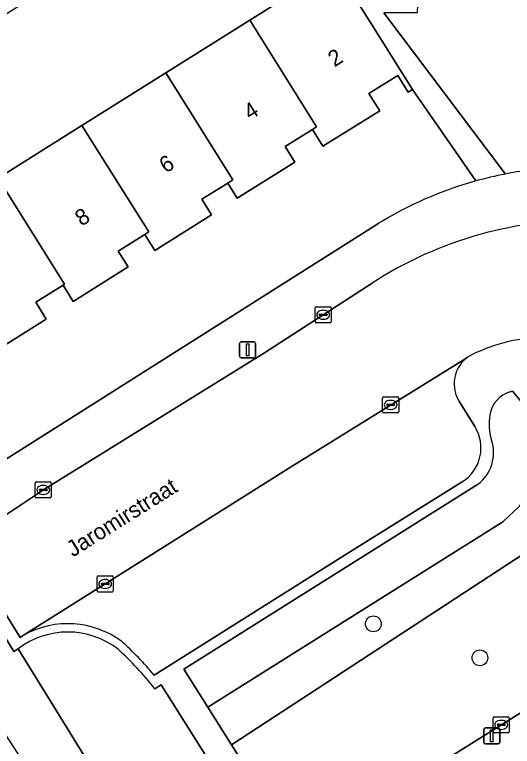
# Model space of a CAD drawing. Extents: x 160077 to 160948, y 386481 to 387498.
# Drawn here: x 160562.4 to 160593.35, y 386604.57 to 386650.13 of the extents above; entities that cross this region are included whole.
import ezdxf

# ---------------------------------------------------------------- set-up
doc = ezdxf.new("R2010")
doc.units = 0
for name, color, linetype in [('IMGEO_Boom', 7, 'Continuous'), ('IMGEO_Erf', 7, 'Continuous'), ('IMGEO_Groenvoorziening', 7, 'Continuous'), ('IMGEO_Kolk', 7, 'Continuous'), ('IMGEO_Lichtmast', 7, 'Continuous'), ('IMGEO_Openbare_ruimte_label', 7, 'Continuous'), ('IMGEO_Pand', 7, 'Continuous'), ('IMGEO_Pand_nummerreeks', 7, 'Continuous'), ('IMGEO_Parkeervlak_open', 7, 'Continuous'), ('IMGEO_Rijbaan_lokaal_open', 7, 'Continuous'), ('IMGEO_Voetpad_open', 7, 'Continuous')]:
    doc.layers.add(name, color=color, linetype=linetype)

msp = doc.modelspace()

# ---------------------------------------------------------------- linework, layer by layer
at = {"layer": 'IMGEO_Boom'}
for centre in [(160584.707, 386612.197), (160591.337, 386610.081)]:
    msp.add_circle(centre, 0.489, dxfattribs=at)
at = {"layer": 'IMGEO_Erf'}
for points in [[(160596.599, 386677.441), (160596.859, 386683.778), (160590.518, 386683.487), (160585.352, 386682.36), (160577.456, 386680.637), (160577.409, 386679.381), (160587.176, 386678.997), (160587.075, 386676.42), (160577.308, 386676.804), (160578.878, 386670.063), (160582.758, 386670.009), (160582.777, 386670.009), (160582.54, 386664.36), (160582.425, 386661.598), (160580.436, 386661.556), (160581.591, 386656.538), (160587.64, 386656.538), (160587.486, 386651.864), (160587.433, 386650.24), (160585.361, 386650.24), (160592.917, 386640.202)], [(160571.801, 386646.502), (160577.019, 386649.777), (160582.341, 386653.116), (160579.976, 386656.903), (160578.066, 386663.398), (160575.291, 386661.665), (160576.679, 386659.497), (160572.571, 386656.868), (160568.508, 386654.268), (160567.121, 386656.435), (160564.914, 386655.022), (160566.242, 386652.948), (160562.134, 386650.319), (160558.071, 386647.719), (160556.684, 386649.886), (160554.477, 386648.473), (160555.805, 386646.399), (160551.696, 386643.77), (160547.634, 386641.17), (160546.247, 386643.337), (160543.649, 386641.674), (160557.447, 386619.675), (160584.982, 386637.094)], [(160591.082, 386639.771), (160587.14, 386645.468), (160586.871, 386645.299), (160586.222, 386646.333), (160584.432, 386645.21), (160585.102, 386644.143), (160581.576, 386641.93), (160580.917, 386642.979), (160579.221, 386641.915), (160579.831, 386640.943), (160576.247, 386638.694), (160575.653, 386639.642), (160574.036, 386638.627), (160574.643, 386637.659), (160571.121, 386635.449), (160570.5, 386636.44), (160568.843, 386635.401), (160569.463, 386634.414), (160566.044, 386632.269), (160565.409, 386633.28), (160563.712, 386632.215), (160564.367, 386631.172), (160560.876, 386628.982)], [(160561.363, 386639.953), (160566.582, 386643.228), (160571.801, 386646.502)]]:
    msp.add_lwpolyline(points, dxfattribs=at)
for centre, radius, start, end in [((160597.405, 386617.02), 23.612, 86.9009, 100.9581), ((160597.413, 386617.056), 23.58, 105.574, 121.8147)]:
    msp.add_arc(centre, radius, start, end, dxfattribs=at)
at = {"layer": 'IMGEO_Groenvoorziening'}
for points in [[(160593.353, 386626.675), (160594.006, 386625.92), (160594.659, 386624.737), (160595.039, 386622.809), (160594.777, 386621.167), (160594.444, 386620.452), (160593.826, 386619.548), (160592.769, 386618.557), (160574.42, 386607.003), (160575.89, 386604.664), (160595.095, 386617.234), (160597.492, 386622.596), (160596.919, 386627.153), (160596.284, 386627.12)], [(160603.036, 386627.12), (160598.454, 386627.234), (160596.919, 386627.153), (160597.492, 386622.596), (160595.095, 386617.234), (160575.89, 386604.664), (160580.063, 386598.024), (160599.738, 386610.339), (160602.696, 386611.053)], [(160591.194, 386620.874), (160572.93, 386609.373), (160574.42, 386607.003), (160592.769, 386618.557), (160593.826, 386619.548), (160594.444, 386620.452), (160594.777, 386621.167), (160595.039, 386622.809), (160594.659, 386624.737), (160594.006, 386625.92), (160593.353, 386626.675), (160593.289, 386626.657), (160593.225, 386626.638)], [(160562.612, 386610.642), (160569.745, 386599.077), (160575.219, 386602.514), (160571.515, 386608.404), (160571.115, 386608.154)]]:
    msp.add_lwpolyline(points, dxfattribs=at)
msp.add_lwpolyline([(160562.612, 386610.642), (160562.354, 386610.475), (160560.029, 386614.281), (160557.174, 386612.458), (160566.971, 386597.336), (160569.745, 386599.077)], close=True, dxfattribs=at)
for centre, radius, start, end in [((160593.714, 386624.927), 1.779, 105.9417, 171.0843), ((160595.098, 386624.624), 3.195, 169.5683, 197.9088), ((160589.706, 386622.857), 2.479, 306.8775, 18.4521), ((160565.705, 386606.587), 5.1, 52.2047, 127.3347), ((160555.455, 386595.923), 19.87, 37.9918, 47.6892)]:
    msp.add_arc(centre, radius, start, end, dxfattribs=at)
at = {"layer": 'IMGEO_Kolk'}
for p, q in [((160581.087, 386631.014), (160581.087, 386631.866)), ((160581.162, 386631.94), (160582.014, 386631.94)), ((160581.575, 386631.72), (160581.6, 386631.72)), ((160582.088, 386631.866), (160582.088, 386631.014)), ((160581.346, 386631.434), (160581.346, 386631.446)), ((160581.784, 386631.397), (160581.386, 386631.397)), ((160581.389, 386631.483), (160581.787, 386631.483)), ((160581.598, 386631.16), (160581.573, 386631.16)), ((160581.83, 386631.446), (160581.83, 386631.434)), ((160582.014, 386630.94), (160581.162, 386630.94)), ((160585.283, 386625.405), (160585.283, 386626.257)), ((160585.358, 386626.331), (160586.21, 386626.331)), ((160585.771, 386626.111), (160585.796, 386626.111)), ((160586.284, 386626.257), (160586.284, 386625.405)), ((160585.542, 386625.825), (160585.542, 386625.837)), ((160585.98, 386625.788), (160585.582, 386625.788)), ((160585.585, 386625.874), (160585.983, 386625.874)), ((160586.026, 386625.837), (160586.026, 386625.825)), ((160586.21, 386625.331), (160585.358, 386625.331)), ((160585.794, 386625.551), (160585.769, 386625.551)), ((160563.678, 386620.108), (160563.678, 386620.96)), ((160563.753, 386621.034), (160564.605, 386621.034)), ((160564.166, 386620.814), (160564.191, 386620.814)), ((160564.679, 386620.96), (160564.679, 386620.108)), ((160563.937, 386620.528), (160563.937, 386620.54)), ((160564.375, 386620.491), (160563.977, 386620.491)), ((160563.98, 386620.577), (160564.378, 386620.577)), ((160564.189, 386620.254), (160564.164, 386620.254)), ((160564.421, 386620.54), (160564.421, 386620.528)), ((160564.605, 386620.034), (160563.753, 386620.034)), ((160567.604, 386615.179), (160568.456, 386615.179)), ((160567.529, 386614.253), (160567.529, 386615.105)), ((160567.788, 386614.673), (160567.788, 386614.685)), ((160567.831, 386614.722), (160568.229, 386614.722)), ((160568.017, 386614.959), (160568.042, 386614.959)), ((160568.272, 386614.685), (160568.272, 386614.673)), ((160568.53, 386615.105), (160568.53, 386614.253)), ((160568.226, 386614.636), (160567.828, 386614.636)), ((160568.04, 386614.399), (160568.015, 386614.399)), ((160568.456, 386614.179), (160567.604, 386614.179)), ((160592.16, 386605.482), (160592.16, 386606.334)), ((160592.235, 386606.408), (160593.087, 386606.408)), ((160592.648, 386606.188), (160592.673, 386606.188)), ((160593.161, 386606.334), (160593.161, 386605.482)), ((160592.419, 386605.902), (160592.419, 386605.914)), ((160592.857, 386605.865), (160592.459, 386605.865)), ((160592.462, 386605.951), (160592.86, 386605.951)), ((160592.671, 386605.628), (160592.646, 386605.628)), ((160592.903, 386605.914), (160592.903, 386605.902)), ((160593.087, 386605.408), (160592.235, 386605.408))]:
    msp.add_line(p, q, dxfattribs=at)
for points in [[(160581.087, 386631.014), (160581.087, 386631.866)], [(160581.162, 386631.94), (160582.014, 386631.94)], [(160582.088, 386631.866), (160582.088, 386631.014)], [(160582.014, 386630.94), (160581.162, 386630.94)], [(160585.283, 386625.405), (160585.283, 386626.257)], [(160585.358, 386626.331), (160586.21, 386626.331)], [(160586.284, 386626.257), (160586.284, 386625.405)], [(160586.21, 386625.331), (160585.358, 386625.331)], [(160563.678, 386620.108), (160563.678, 386620.96)], [(160563.753, 386621.034), (160564.605, 386621.034)], [(160564.679, 386620.96), (160564.679, 386620.108)], [(160564.605, 386620.034), (160563.753, 386620.034)], [(160567.604, 386615.179), (160568.456, 386615.179)], [(160567.529, 386614.253), (160567.529, 386615.105)], [(160568.53, 386615.105), (160568.53, 386614.253)], [(160568.456, 386614.179), (160567.604, 386614.179)], [(160592.16, 386605.482), (160592.16, 386606.334)], [(160592.235, 386606.408), (160593.087, 386606.408)], [(160593.161, 386606.334), (160593.161, 386605.482)], [(160593.087, 386605.408), (160592.235, 386605.408)]]:
    msp.add_lwpolyline(points, dxfattribs=at)
for centre, radius, start, end in [((160581.164, 386631.864), 0.0765, 91.552, 178.448), ((160581.164, 386631.864), 0.0765, 91.552, 178.448), ((160582.012, 386631.864), 0.0765, 1.552, 88.448), ((160582.012, 386631.864), 0.0765, 1.552, 88.448), ((160581.386, 386631.443), 0.0403, 85.8775, 175.7526), ((160581.383, 386631.433), 0.0366, 178.938, 274.7102), ((160581.787, 386631.44), 0.043, 264.8664, 352.4533), ((160581.791, 386631.445), 0.0386, 1.7309, 96.639), ((160581.164, 386631.016), 0.0765, 181.552, 268.448), ((160581.164, 386631.016), 0.0765, 181.552, 268.448), ((160582.012, 386631.016), 0.0765, 271.552, 358.448), ((160582.012, 386631.016), 0.0765, 271.552, 358.448), ((160585.36, 386626.255), 0.0765, 91.552, 178.448), ((160585.36, 386626.255), 0.0765, 91.552, 178.448), ((160586.208, 386626.255), 0.0765, 1.552, 88.448), ((160586.208, 386626.255), 0.0765, 1.552, 88.448), ((160585.582, 386625.834), 0.0403, 85.8775, 175.7526), ((160585.579, 386625.824), 0.0366, 178.938, 274.7102), ((160585.983, 386625.831), 0.043, 264.8664, 352.4533), ((160585.987, 386625.836), 0.0386, 1.7309, 96.639), ((160585.36, 386625.407), 0.0765, 181.552, 268.448), ((160585.36, 386625.407), 0.0765, 181.552, 268.448), ((160586.208, 386625.407), 0.0765, 271.552, 358.448), ((160586.208, 386625.407), 0.0765, 271.552, 358.448), ((160563.755, 386620.958), 0.0765, 91.552, 178.448), ((160563.755, 386620.958), 0.0765, 91.552, 178.448), ((160564.603, 386620.958), 0.0765, 1.552, 88.448), ((160564.603, 386620.958), 0.0765, 1.552, 88.448), ((160563.977, 386620.537), 0.0403, 85.8775, 175.7526), ((160563.974, 386620.527), 0.0366, 178.938, 274.7102), ((160564.378, 386620.534), 0.043, 264.8664, 352.4533), ((160564.382, 386620.539), 0.0386, 1.7309, 96.639), ((160563.755, 386620.11), 0.0765, 181.552, 268.448), ((160563.755, 386620.11), 0.0765, 181.552, 268.448), ((160564.603, 386620.11), 0.0765, 271.552, 358.448), ((160564.603, 386620.11), 0.0765, 271.552, 358.448), ((160567.606, 386615.103), 0.0765, 91.552, 178.448), ((160567.606, 386615.103), 0.0765, 91.552, 178.448), ((160568.454, 386615.103), 0.0765, 1.552, 88.448), ((160568.454, 386615.103), 0.0765, 1.552, 88.448), ((160567.828, 386614.682), 0.0403, 85.8775, 175.7526), ((160567.825, 386614.672), 0.0366, 178.938, 274.7102), ((160568.229, 386614.679), 0.043, 264.8664, 352.4533), ((160568.233, 386614.684), 0.0386, 1.7309, 96.639), ((160567.606, 386614.255), 0.0765, 181.552, 268.448), ((160567.606, 386614.255), 0.0765, 181.552, 268.448), ((160568.454, 386614.255), 0.0765, 271.552, 358.448), ((160568.454, 386614.255), 0.0765, 271.552, 358.448), ((160592.237, 386606.332), 0.0765, 91.552, 178.448), ((160592.237, 386606.332), 0.0765, 91.552, 178.448), ((160593.085, 386606.332), 0.0765, 1.552, 88.448), ((160593.085, 386606.332), 0.0765, 1.552, 88.448), ((160592.459, 386605.911), 0.0403, 85.8775, 175.7526), ((160592.456, 386605.901), 0.0366, 178.938, 274.7102), ((160592.86, 386605.908), 0.043, 264.8664, 352.4533), ((160592.864, 386605.913), 0.0386, 1.7309, 96.639), ((160592.237, 386605.484), 0.0765, 181.552, 268.448), ((160592.237, 386605.484), 0.0765, 181.552, 268.448), ((160593.085, 386605.484), 0.0765, 271.552, 358.448), ((160593.085, 386605.484), 0.0765, 271.552, 358.448)]:
    msp.add_arc(centre, radius, start, end, dxfattribs=at)
for centre, major_axis, ratio, start_param, end_param in [((160581.574, 386631.44), (-0.387, 0.002), 0.722429, 4.712389, 7.853982), ((160581.599, 386631.44), (-0.39, 0.002), 0.717154, 1.570796, 4.712389), ((160585.77, 386625.831), (-0.387, 0.002), 0.722429, 4.712389, 7.853982), ((160585.795, 386625.831), (-0.39, 0.002), 0.717154, 1.570796, 4.712389), ((160564.165, 386620.534), (-0.387, 0.002), 0.722429, 4.712389, 7.853982), ((160564.19, 386620.534), (-0.39, 0.002), 0.717154, 1.570796, 4.712389), ((160568.016, 386614.679), (-0.387, 0.002), 0.722429, 4.712389, 7.853982), ((160568.041, 386614.679), (-0.39, 0.002), 0.717154, 1.570796, 4.712389), ((160592.647, 386605.908), (-0.387, 0.002), 0.722429, 4.712389, 7.853982), ((160592.672, 386605.908), (-0.39, 0.002), 0.717154, 1.570796, 4.712389)]:
    msp.add_ellipse(centre, major_axis=major_axis, ratio=ratio, start_param=start_param, end_param=end_param, dxfattribs=at)
at = {"layer": 'IMGEO_Lichtmast'}
for p, q in [((160576.489, 386629.76), (160577.279, 386629.76)), ((160577.279, 386629.76), (160576.489, 386629.76)), ((160576.389, 386628.86), (160576.389, 386629.66)), ((160576.389, 386629.66), (160576.389, 386628.86)), ((160577.379, 386629.66), (160577.379, 386628.86)), ((160577.379, 386628.86), (160577.379, 386629.66)), ((160577.279, 386628.76), (160576.489, 386628.76)), ((160576.489, 386628.76), (160577.279, 386628.76)), ((160591.577, 386604.817), (160591.577, 386605.617)), ((160591.577, 386605.617), (160591.577, 386604.817)), ((160591.677, 386605.717), (160592.467, 386605.717)), ((160592.467, 386605.717), (160591.677, 386605.717)), ((160592.567, 386605.617), (160592.567, 386604.817)), ((160592.567, 386604.817), (160592.567, 386605.617)), ((160592.467, 386604.717), (160591.677, 386604.717)), ((160591.677, 386604.717), (160592.467, 386604.717))]:
    msp.add_line(p, q, dxfattribs=at)
for points in [[(160576.809, 386629.635), (160576.959, 386629.635), (160576.959, 386628.885), (160576.809, 386628.885), (160576.809, 386629.635)], [(160591.997, 386605.592), (160592.147, 386605.592), (160592.147, 386604.842), (160591.997, 386604.842), (160591.997, 386605.592)]]:
    msp.add_lwpolyline(points, dxfattribs=at)
for centre, start, end in [((160576.489, 386629.66), 90, 180), ((160576.489, 386629.66), 90, 180), ((160577.279, 386629.66), 0, 90), ((160577.279, 386629.66), 360, 90), ((160576.489, 386628.86), 180, 270), ((160576.489, 386628.86), 180, 270), ((160577.279, 386628.86), 270, 0), ((160577.279, 386628.86), 270, 0), ((160591.677, 386605.617), 90, 180), ((160591.677, 386605.617), 90, 180), ((160592.467, 386605.617), 0, 90), ((160592.467, 386605.617), 360, 90), ((160591.677, 386604.817), 180, 270), ((160591.677, 386604.817), 180, 270), ((160592.467, 386604.817), 270, 0), ((160592.467, 386604.817), 270, 0)]:
    msp.add_arc(centre, 0.1, start, end, dxfattribs=at)
at = {"layer": 'IMGEO_Pand'}
for points in [[(160580.917, 386642.979), (160581.576, 386641.93), (160585.102, 386644.143), (160584.432, 386645.21), (160586.222, 386646.333), (160586.871, 386645.299), (160587.14, 386645.468), (160584.482, 386649.704), (160582.341, 386653.116), (160577.019, 386649.777), (160581.18, 386643.144)], [(160575.653, 386639.642), (160576.247, 386638.694), (160579.831, 386640.943), (160579.221, 386641.915), (160580.917, 386642.979), (160581.18, 386643.144), (160577.019, 386649.777), (160571.801, 386646.502), (160575.977, 386639.845)], [(160570.5, 386636.44), (160571.121, 386635.449), (160574.643, 386637.659), (160574.036, 386638.627), (160575.653, 386639.642), (160575.977, 386639.845), (160571.801, 386646.502), (160566.582, 386643.228), (160570.744, 386636.593)], [(160565.409, 386633.28), (160566.044, 386632.269), (160569.463, 386634.414), (160568.843, 386635.401), (160570.5, 386636.44), (160570.744, 386636.593), (160566.582, 386643.228), (160561.363, 386639.953), (160565.51, 386633.343)], [(160565.51, 386633.343), (160561.363, 386639.953), (160556.145, 386636.679), (160560.26, 386629.963), (160560.876, 386628.982), (160564.367, 386631.172), (160563.712, 386632.215), (160565.409, 386633.28)]]:
    msp.add_lwpolyline(points, close=True, dxfattribs=at)
at = {"layer": 'IMGEO_Parkeervlak_open'}
for points in [[(160590.451, 386628.713), (160579.655, 386622.005), (160563.001, 386611.512)], [(160591.023, 386624.478), (160590.057, 386626.025)], [(160571.076, 386609.005), (160583.069, 386616.562), (160590.227, 386621.033)]]:
    msp.add_lwpolyline(points, dxfattribs=at)
for centre, radius, start, end in [((160591.84, 386627.137), 2.101, 131.3763, 211.9459), ((160588.905, 386623.153), 2.499, 301.9537, 32.0255), ((160565.705, 386606.587), 5.619, 53.6143, 118.7663), ((160555.635, 386596.095), 20.127, 39.8995, 48.2475)]:
    msp.add_arc(centre, radius, start, end, dxfattribs=at)
at = {"layer": 'IMGEO_Rijbaan_lokaal_open'}
msp.add_lwpolyline([(160584.627, 386633.411), (160577.938, 386629.07), (160564.253, 386620.579), (160561.375, 386618.67), (160561.3, 386618.623), (160559.077, 386617.225), (160560.499, 386614.99), (160560.685, 386614.698), (160560.664, 386614.686), (160562.742, 386611.341), (160563.001, 386611.512), (160579.655, 386622.005), (160590.451, 386628.713), (160590.568, 386628.809)], dxfattribs=at)
for centre, radius, start, end in [((160597.847, 386613.046), 24.279, 88.147, 122.9902), ((160595.473, 386619.634), 10.404, 91.3738, 118.1302)]:
    msp.add_arc(centre, radius, start, end, dxfattribs=at)
at = {"layer": 'IMGEO_Voetpad_open'}
for points in [[(160571.203, 386659.048), (160575.291, 386661.665), (160578.066, 386663.398), (160579.976, 386656.903), (160582.341, 386653.116), (160584.482, 386649.704), (160587.14, 386645.468), (160591.082, 386639.771)], [(160592.917, 386640.202), (160585.361, 386650.24)], [(160584.982, 386637.094), (160557.447, 386619.675), (160557.044, 386619.42), (160555.856, 386618.671), (160554.264, 386617.669), (160551.588, 386615.983)], [(160549.014, 386616.631), (160548.99, 386616.571), (160551.888, 386612.662), (160559.077, 386617.225), (160561.3, 386618.623), (160561.375, 386618.67), (160564.253, 386620.579), (160577.938, 386629.07), (160584.627, 386633.411)], [(160590.568, 386628.809), (160590.451, 386628.713)], [(160593.225, 386626.638), (160593.289, 386626.657), (160593.353, 386626.675)], [(160590.057, 386626.025), (160591.023, 386624.478)], [(160590.227, 386621.033), (160583.069, 386616.562), (160571.076, 386609.005)], [(160571.115, 386608.154), (160571.515, 386608.404), (160575.219, 386602.514), (160578.617, 386597.11), (160580.063, 386598.024), (160575.89, 386604.664), (160574.42, 386607.003), (160572.93, 386609.373), (160591.194, 386620.874)], [(160563.001, 386611.512), (160562.742, 386611.341), (160560.664, 386614.686), (160560.272, 386614.436), (160560.029, 386614.281), (160562.354, 386610.475), (160562.612, 386610.642)], [(160602.696, 386611.053), (160599.738, 386610.339), (160580.063, 386598.024), (160578.617, 386597.11), (160571.34, 386592.347), (160571.167, 386592.241), (160567.76, 386590.144)]]:
    msp.add_lwpolyline(points, dxfattribs=at)
for centre, radius, start, end in [((160597.394, 386617.021), 23.609, 100.93, 105.5057), ((160597.394, 386617.021), 23.609, 100.93, 105.5057), ((160597.405, 386617.02), 23.612, 86.9009, 100.9581), ((160597.413, 386617.056), 23.58, 105.574, 121.8147), ((160597.847, 386613.046), 24.279, 88.147, 122.9902), ((160595.473, 386619.634), 10.404, 91.3738, 118.1302), ((160591.84, 386627.137), 2.101, 131.3763, 211.9459), ((160593.714, 386624.927), 1.779, 105.9417, 171.0843), ((160595.098, 386624.624), 3.195, 169.5683, 197.9088), ((160588.905, 386623.153), 2.499, 301.9537, 32.0255), ((160589.706, 386622.857), 2.479, 306.8775, 18.4521), ((160565.705, 386606.587), 5.619, 53.6143, 118.7663), ((160565.705, 386606.587), 5.1, 52.2047, 127.3347), ((160555.635, 386596.095), 20.127, 39.8995, 48.2475), ((160555.455, 386595.923), 19.87, 37.9918, 47.6892)]:
    msp.add_arc(centre, radius, start, end, dxfattribs=at)

# ---------------------------------------------------------------- texts
at = {"layer": 'IMGEO_Openbare_ruimte_label'}
msp.add_text('Jaromirstraat', height=1, rotation=32.2119, dxfattribs=at).set_placement((160566.022, 386616.325))
at = {"layer": 'IMGEO_Pand_nummerreeks'}
for s, p in [('2', (160582.29, 386646.834)), ('4', (160577.045, 386643.529)), ('6', (160571.798, 386640.224)), ('8', (160566.556, 386636.92))]:
    msp.add_text(s, height=1, rotation=32.213, dxfattribs=at).set_placement(p)

doc.saveas('drawing.dxf')
